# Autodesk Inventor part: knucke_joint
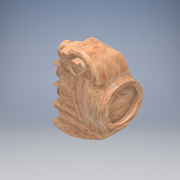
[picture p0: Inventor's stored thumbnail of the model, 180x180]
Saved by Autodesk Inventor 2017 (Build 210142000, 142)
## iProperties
Created: 2017-05
Part Number: knucke_joint
Material: Generic
Document SubType Name: Modeling
Designer: alez_
Density: 1 g/cm^3
Appearance: Birch - Natural Polished
Created: 2017-06
Part Number: knucke_joint_3DPrint
Appearance: Default
Author: alez_
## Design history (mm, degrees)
sketch "Sketch1"
  geometry: C1 r 7.5 at (0, 0); C2 r 5.25 at (0, 0); 1 further point
  constraints: 2 centre point, 2 coincident
  dimensions: "d0" = 15 diameter of C1; "d1" = 10.5 diameter of C2
extrude "Extrusion1" new body sketch "Sketch1" distance "d2" = 1; taper "d3" = 0 deg
sketch "Sketch2"
  geometry: L1 (0, 9.547)-(-4.25, 9.547); L2 (-4.25, 9.547)-(4.25, 9.547); L3 (4.25, 9.547)-(4.25, 0); L4 (4.25, 0)-(-4.25, 0); L5 (-4.25, 0)-(-4.25, 9.547); 1 further point
  constraints: 10 end point, 3 perpendicular, 1 point on line
  dimensions: "d4" = 4.25 distance of L1.start L1.end; "d5" = 8.5 distance of L1.end L2.end
extrude "Extrusion2" cut sketch "Sketch2" distance "d6" = 1; taper "d7" = 0 deg
sketch "Sketch3"
  geometry: L1 (-4.25, 6.18)-(-4.25, 7.649); L2 (4.25, 6.18)-(4.25, 7.649); C1 r 7.5 at (0, 0); A1 r 8.75 centre (0, 0) between (-4.25, 7.649) and (4.25, 7.649); A2 r 7.5 centre (0, 0) between (-4.25, 6.18) and (4.25, 6.18) reference; 1 further point
  constraints: 4 end point, 2 centre point, 2 coincident, 2 point on circle, 1 vertical
extrude "Extrusion3" join sketch "Sketch3" distance "d9" = 4; taper "d10" = 0 deg
sketch "Sketch4"
  geometry: C1 r 8.75 at (0, 0); 1 further point
  constraints: 1 centre point, 1 coincident
extrude "Extrusion4" join sketch "Sketch4" distance "d11" = 4; taper "d12" = 0 deg
sketch "Sketch5"
  geometry: L1 (-35.933, 12.752)-(-42.214, 19.08); L2 (-42.214, 19.08)-(-43.387, 22.598); L3 (-43.387, 22.598)-(-57.456, 20.487); L4 (-57.456, 20.487)-(-64.49, 16.267); L5 (-64.49, 16.267)-(-70, 4.25); L6 (-70, 4.25)-(-70, -55.75); L7 (0, -22)-(0, -42); L8 (0, -42)-(0, -62); L9 (-70, -55.75)-(-70, -62.205); L10 (-70, -62.205)-(-60.973, -70.522); L11 (-60.973, -70.522)-(-35, -74.178); L12 (-35, -74.178)-(-11.686, -72.505); L13 (-11.686, -72.505)-(0, -68.799); L14 (0, -62)-(0, -68.799); L15 (-8, 8.75)-(-8, -8.75) reference; L16 (0, -8.75)-(-8, -8.75); L17 (-8, 8.75)-(-14.863, 9.705); L18 (-14.863, 9.705)-(-17.626, 10.046); L19 (-17.626, 10.046)-(-25.97, 11.171); L20 (-25.97, 11.171)-(-35.933, 12.752); L21 (-8, -8.75)-(-8, 8.75); L22 (0, -22)-(0, -8.75)
  constraints: 14 end point, 4 vertical, 1 collinear, 1 horizontal, 1 point on line, 9 other
  dimensions: "d14" = 60 distance of L5.end L6.end; "d16" = 20 distance of L7.start L7.end; "d17" = 20 distance of L7.end L8.end
extrude "Extrusion5" join sketch "Sketch5" stored distance "d18" = 30; taper "d19" = 0 deg
sketch "Sketch6"
  geometry: L1 (-8.75, 15)-(-30.75, 15); L2 (-30.75, 15)-(-41.25, 15); L3 (-41.25, 15)-(-30.75, 15); L4 (-30.75, 15)-(-20.25, 15); L5 (-20.25, 15)-(-20.25, 0); L6 (-20.25, 15)-(-41.25, 15); L7 (-41.25, 15)-(-41.25, 0); L8 (-41.25, 0)-(-41.25, -15); L9 (-20.25, 0)-(-20.25, -15); L10 (-20.25, -15)-(-41.25, -15); 1 further point
  constraints: 20 end point, 2 equal length, 2 perpendicular, 2 vertical, 1 horizontal, 1 point on line
  dimensions: "d20" = 22 distance of L1.start L1.end; "d23" = 10.5 distance of L1.end L2.end; "d24" = 10.5 distance of L1.end L4.end
extrude "Extrusion6" cut sketch "Sketch6" distance "d25" = 30; taper "d26" = 0 deg
sketch "Sketch7"
  geometry: L1 (-30.75, 15)-(-52.75, 15); L2 (-52.75, 15)-(-43.25, 15); L3 (-43.25, -15)-(-43.25, 15); L4 (-52.75, 15)-(-62.25, 15); L5 (-62.25, 15)-(-62.25, -15); L6 (-62.25, -15)-(-43.25, -15); L7 (-64.5, -15)-(-4.5, -15) reference; 1 further point
  constraints: 12 end point, 1 collinear, 1 perpendicular
  dimensions: "d27" = 22 distance of L1.start L1.end; "d28" = 9.5 distance of L1.end L2.end; "d32" = 9.5 distance of L1.end L4.end
extrude "Extrusion8" cut sketch "Sketch7" distance "d33" = 10; taper "d34" = 0 deg
sketch "Sketch8"
  geometry: L1 (70, -4.25)-(70, 55.75) reference; L2 (70, 55.75)-(70, 56.61); L3 (70, 56.61)-(69.806, 58.009); L4 (69.806, 58.009)-(69.421, 59.444); L5 (69.421, 59.444)-(68.896, 60.634); L6 (68.896, 60.634)-(67.987, 61.928); L7 (67.987, 61.928)-(66.307, 63.678); L8 (66.307, 63.678)-(64.033, 65.568); L9 (64.033, 65.568)-(61.093, 67.142); L10 (61.093, 67.142)-(57.874, 68.962); L11 (57.874, 68.962)-(54.55, 70.221); L12 (54.55, 70.221)-(50.281, 72.566); L13 (50.281, 72.566)-(45.487, 74.7); L14 (45.487, 74.7)-(36.592, 78.514); L15 (36.592, 78.514)-(27.96, 80.12); L16 (27.96, 80.12)-(16.015, 83.834); L17 (16.015, 83.834)-(0, 79.718); L18 (0, 68.799)-(0, 53.5) reference; L19 (0, 68.799)-(0, 79.718); L20 (70, 55.75)-(0, 68.799); 1 further point
  constraints: 4 end point, 2 collinear, 3 other
extrude "Extrusion9" join sketch "Sketch8" distance "d35" = 30; taper "d36" = 0 deg
sketch "Sketch9"
  geometry: L1 (-62.25, 15)-(-43.25, 15) reference; L2 (-52.75, 15)-(-75.75, 15); L3 (-75.75, 15)-(-68.75, 15); L4 (-88.468, 15)-(-62.25, 15) reference; L5 (-68.75, 15)-(-82.75, 15); L6 (-82.75, 15)-(-82.75, -15); L7 (-62.25, -15)-(-88.468, -15) reference; L8 (-82.75, -15)-(-68.75, -15); L9 (-68.75, -15)-(-68.75, 15); 1 further point
  constraints: 12 end point, 4 point on line, 2 perpendicular, 1 collinear, 1 midpoint
  dimensions: "d37" = 23 distance of L2.start L2.end; "d38" = 7 distance of L2.end L3.end; "d39" = 14 distance of L3.end L5.end
extrude "Extrusion10" cut sketch "Sketch9" distance "d40" = 30; taper "d41" = 0 deg
sketch "Sketch10"
  geometry: C1 r 10.5 at (-30.75, 0); C2 r 9.5 at (-52.75, 0); C3 r 7 at (-75.75, 0); 1 further point
  constraints: 3 centre point
extrude "Extrusion11" join sketch "Sketch10" distance "d42" = 8; taper "d43" = 0 deg
sketch "Sketch11"
  geometry: L1 (-25.65, 3.699)-(-25.65, 12.987); L2 (-25.65, 12.987)-(-35.85, 12.987); L3 (-35.85, 12.987)-(-35.85, 3.699); L4 (-48.075, 3.39)-(-48.075, 12.987); L5 (-48.075, 12.987)-(-57.425, 12.987); L6 (-57.425, 12.987)-(-57.425, 3.39); L7 (-71.925, 2.774)-(-71.925, 12.987); L8 (-71.925, 12.987)-(-79.575, 12.987); L9 (-79.575, 12.987)-(-79.575, 2.774); A1 r 10.5 centre (-30.75, 0) between (-20.25, 0) and (-41.25, 0) reference; A2 r 6.3 centre (-30.75, 0) between (-35.85, 3.699) and (-25.65, 3.699); A3 r 9.5 centre (-52.75, 0) between (-43.25, 0) and (-62.25, 0) reference; A4 r 5.775 centre (-52.75, 0) between (-57.425, 3.39) and (-48.075, 3.39); A5 r 7 centre (-75.75, 0) between (-68.75, 0) and (-82.75, 0) reference; A6 r 4.725 centre (-75.75, 0) between (-79.575, 2.774) and (-71.925, 2.774); 1 further point
  constraints: 18 end point, 6 point on circle, 4 perpendicular, 4 point on line, 3 centre point, 3 coincident
  dimensions: "d44" = 12.6 diameter of A2; "d45" = 11.55 diameter of A4; "d46" = 9.45 diameter of A6
extrude "Extrusion12" cut sketch "Sketch11" distance "d53" = 4; taper "d54" = 0 deg
sketch "Sketch12"
  geometry: L1 (-79.575, 5.562)-(-79.575, 5.863); L2 (-71.925, 5.863)-(-71.925, 5.562); L3 (-57.425, 6.798)-(-57.425, 8.27); C1 r 6.75 at (-75.75, 0); A1 r 9 centre (-30.75, 0) between (-35.85, 7.416) and (-25.65, 7.416); A2 r 8.25 centre (-52.75, 0) between (-57.425, 6.798) and (-48.075, 6.798); A3 r 6.75 centre (-75.75, 0) between (-79.575, 5.562) and (-71.925, 5.562); 10 further points
  constraints: 6 coincident, 6 end point, 6 point on circle, 4 centre point, 1 vertical, 6 other
  dimensions: "d55" = 18 diameter of A1; "d56" = 16.5 diameter of A2; "d57" = 13.5 diameter of A3
extrude "Extrusion13" cut sketch "Sketch12" distance "d58" = 3; taper "d59" = 0 deg
fillet "Fillet1" dims "d60" = 5
fillet "Fillet2" dims "d61" = 2
fillet "Fillet3" dims "d62" = 2
fillet "Fillet4" dims "d63" = 2
sketch "Sketch13"
  geometry: L1 (0, 0)-(60, 0) reference; 2 further points; 1 other entity
  constraints: 1 horizontal, 2 other
extrude "Extrusion14" join sketch "Sketch13" distance "d64" = 14; taper "d65" = 0 deg
fillet "Fillet5" dims "d66" = 60
fillet "Fillet6" dims "d67" = 20
fillet "Fillet7" dims "d68" = 15
fillet "Fillet8" dims "d69" = 15
fillet "Fillet9" dims "d70" = 60
fillet "Fillet10" dims "d71" = 25
fillet "Fillet11" dims "d72" = 25
sketch "Sketch19"
  geometry: L1 (70, 4.25)-(67.71, 17.695); L2 (67.71, 17.695)-(59.243, 27.836); L3 (59.243, 27.836)-(52.103, 32.318); L4 (52.103, 32.318)-(41.187, 33.204); L5 (41.187, 33.204)-(33.573, 29.541); L6 (33.573, 29.541)-(29.956, 25.64); L7 (29.956, 25.64)-(29.956, 18.122); L8 (29.956, 18.122)-(31.238, 14.306); L9 (31.238, 14.306)-(39.133, 9.916); L10 (39.133, 9.916)-(55.431, 3.477); L11 (55.431, 3.477)-(70, 4.25); 1 further point
  constraints: 1 vertical, 2 other
extrude "Extrusion20" join sketch "Sketch19" distance "d89" = 13; taper "d90" = 0 deg
sketch "Sketch20"
  geometry: L1 (70, 4.25)-(67.71, 17.695); L2 (67.71, 17.695)-(59.243, 27.836); L3 (59.243, 27.836)-(52.103, 32.318); L4 (52.103, 32.318)-(41.187, 33.204); L5 (41.187, 33.204)-(33.573, 29.541); L6 (33.573, 29.541)-(29.956, 25.64); L7 (29.956, 25.64)-(29.956, 18.122); L8 (29.956, 18.122)-(31.238, 14.306); L9 (31.238, 14.306)-(39.133, 9.916); L10 (39.133, 9.916)-(55.431, 3.477); L11 (55.431, 3.477)-(70, 4.25); 2 further points
  constraints: 1 vertical, 2 other
extrude "Extrusion21" join sketch "Sketch20" distance "d91" = 43; taper "d92" = 0 deg
sketch "Sketch21"
  geometry: L1 (-61.059, 28)-(-65.116, 27.222); L2 (-65.116, 27.222)-(-69.948, 26.302); L3 (-69.948, 26.302)-(-75.699, 24.155); L4 (-75.699, 24.155)-(-79.074, 21.701); L5 (-79.074, 21.701)-(-81.911, 17.943); L6 (-81.911, 17.943)-(-85.515, 10.274); L7 (-85.515, 10.274)-(-87.739, 4.062); L8 (-87.739, 4.062)-(-89.12, 2.682); L9 (-89.12, 2.682)-(-93.798, 6.44); L10 (-93.798, 6.44)-(-98.092, 10.811); L11 (-98.092, 10.811)-(-102.464, 20.32); L12 (-102.464, 20.32)-(-101.85, 28.679); L13 (-101.85, 28.679)-(-98.399, 35.581); L14 (-98.399, 35.581)-(-89.887, 40.796); L15 (-89.887, 40.796)-(-81.144, 42.483); L16 (-81.144, 42.483)-(-71.481, 42.483); L17 (-71.481, 42.483)-(-65.116, 41.18); L18 (-65.116, 41.18)-(-58.368, 33.971); L19 (-58.368, 33.971)-(-61.059, 28); 1 further point
  constraints: 1 horizontal, 6 other
extrude "Extrusion22" cut sketch "Sketch21" distance "d93" = 50; taper "d94" = 0 deg
fillet "Fillet14" dims "d95" = 5
sketch "Sketch22"
  geometry: C1 r 8.5 at (48.724, 18.001); 1 further point
  constraints: 1 centre point
  dimensions: "d96" = 17 diameter of C1
extrude "Extrusion23" join sketch "Sketch22" distance "d97" = 8; taper "d98" = 0 deg
sketch "Sketch23"
  geometry: L1 (4.847, -2.018)-(9.895, 1.069); L2 (0.413, 5.234)-(5.461, 8.321); L3 (5.461, 8.321)-(9.895, 1.069); A1 r 5.25 centre (0, 0) between (-2.475, 4.63) and (4.847, -2.018); A2 r 5.25 centre (0, 0) between (-0.828, 5.184) and (4.847, -2.018); A3 r 5.25 centre (0, 0) between (0.413, 5.234) and (4.847, -2.018); 2 further points
  constraints: 8 point on circle, 6 end point, 3 centre point, 3 coincident, 1 perpendicular
  dimensions: "d99" = 10.5 diameter of A1
extrude "Extrusion24" cut sketch "Sketch23" distance "d102" = 4; taper "d103" = 0 deg
sketch "Sketch24"
  geometry: C1 r 7.5 at (0, 0); 2 further points
  constraints: 1 centre point, 1 coincident
  dimensions: "d104" = 15 diameter of C1
extrude "Extrusion25" cut sketch "Sketch24" distance "d105" = 3; taper "d106" = 0 deg
fillet "Fillet15" dims "d107" = 1
sketch "Sketch25"
  geometry: C1 r 25 at (-30, 13); 4 further points; 1 other entity
  constraints: 1 centre point, 1 coincident, 1 other
  dimensions: "d114" = 50 diameter of C1
extrude "Extrusion26" join sketch "Sketch25" distance "d115" = 8; taper "d116" = 0 deg
sketch "Sketch26"
  geometry: C1 r 25 at (0, 0) reference; C2 r 20 at (0, 0); 1 further point
  constraints: 1 centre point, 1 coincident
  dimensions: "d117" = 40 diameter of C2
extrude "Extrusion27" cut sketch "Sketch26" distance "d118" = 2.5; taper "d119" = 0 deg
sketch "Sketch27"
  geometry: C1 r 22.5 at (0, 0); 1 further point
  constraints: 1 centre point
  dimensions: "d120" = 45 diameter of C1
extrude "Extrusion28" cut sketch "Sketch27" distance "d121" = 5.5; taper "d122" = 0 deg
fillet "Fillet16" dims "d123" = 3
workplane "Work Plane1"
sketch "Sketch28"
  geometry: L1 (27.052, 9.848)-(27.052, 0) reference; L2 (8.302, 0)-(27.052, 0) reference; L3 (27.052, 3.081)-(24.803, 0); L4 (24.803, 0)-(19.484, -2.001); L5 (19.484, -2.001)-(14.638, -2.001); L6 (14.638, -2.001)-(10.147, 3.081); L7 (10.147, 3.081)-(7.665, 3.081); L8 (7.665, 3.081)-(4.829, -0.464); L9 (4.829, -0.464)-(-4.035, -2.764); L10 (-4.035, -2.764)-(-10.063, -2.764); L11 (-10.063, -2.764)-(-14.435, 1.072); L12 (-14.435, 1.072)-(-17.391, -0.585); L13 (-17.391, -0.585)-(-20.031, -1.359); L14 (-20.031, -1.359)-(-24.836, -2.194); L15 (-24.836, -2.194)-(-32.163, -2.194); L16 (-32.163, -2.194)-(-36.418, 3.081); L17 (-36.418, 3.081)-(-40.318, 3.447); L18 (-40.318, 3.447)-(-44.455, 0.245); L19 (-44.455, 0.245)-(-49.419, -1.646); L20 (-49.419, -1.646)-(-57.101, 3.447); L21 (-57.101, 3.447)-(-59.346, 8.459); L22 (-59.346, 8.459)-(-63.01, 8.459); L23 (-63.01, 8.459)-(-64.192, 8.459); L24 (-64.192, 8.459)-(-66.438, 3.447); L25 (-66.438, 3.447)-(-66.438, -2.954); L26 (-66.438, -2.954)-(-64.074, -10.746); L27 (-64.074, -10.746)-(-54.619, -15.71); L28 (-54.619, -15.71)-(-33.464, -18.901); L29 (-33.464, -18.901)-(-7.699, -18.074); L30 (-7.699, -18.074)-(19.721, -15.119); L31 (19.721, -15.119)-(29.648, -13.347); L32 (29.648, -13.347)-(34.848, -9.683); L33 (34.848, -9.683)-(27.052, 3.081); 6 further points; 3 other entities
  constraints: 6 horizontal, 2 point on line, 1 vertical, 7 other
extrude "Extrusion29" cut sketch "Sketch28" distance "d125" = 39.25; taper "d127" = 0 deg; dims "d126" = 19.625, "d128" = 0
fillet "Fillet17" dims "d129" = 1
body "Solid1"
other parameters: "d124" = 190 deg
